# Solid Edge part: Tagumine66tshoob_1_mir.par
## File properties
Author: KULL
Template: Iso Metric Part.par
Last saved by: KULL
Revision: 2
Application: Solid Edge
Density: 2712,000 kg/m^3
Accuracy: 0,990
Username: KULL
Material: Aluminum, 1060
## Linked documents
Tagumine66tshoob_1.par
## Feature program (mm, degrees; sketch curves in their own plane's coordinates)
part copy "CopiedPart_1"
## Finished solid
Body 1: solid body, 578 faces, 1234 edges, 670 vertices.
  Faces by surface: blend 365, spline 59, sphere 55, plane 30, cylinder 28, torus 27, offset 13, cone 1
  Edges by curve: intersection 729, circle 467, line 37, curve on surface 1
Bounding box of the edges (mm; curved faces can reach further): 84.000 x 73.183 x 18.177, from (-384.46, -113.1829, -2.3663) to (-300.46, -40, 15.811).
Cylindrical faces by radius (mm): R0.4 x6, R1.5 x1, R2.5 x2, R2.9732 x1, R5 x4, R7 x2, R7.9504 x1, R8.5905 x1, R9.9504 x1, R10.5905 x1, R10.611 x1, R12.611 x1, R20 x2, R21.7545 x1, R22 x2, R23.7545 x1
Conical faces (half-angle, radius in mm at the cone's reference point): 40.1033 deg R3.865 x1
Toroidal faces (ring radius, tube radius in mm): R2.5732 r0.4 x2, R3.9041 r0.4 x1, R4.4 r0.6 x8, R4.5371 r1.485 x1, R4.996 r0.6 x1, R5.3 r0.3 x8, R5.7982 r0.6 x1, R6 r1 x4, R6.9857 r1 x1
Spherical faces by radius (mm): R0.1 x53, R4 x1, R6 x1
Planar faces by outward normal: +x 9, -x 9, oblique 12
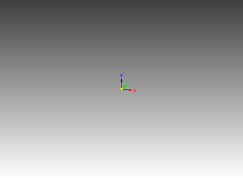
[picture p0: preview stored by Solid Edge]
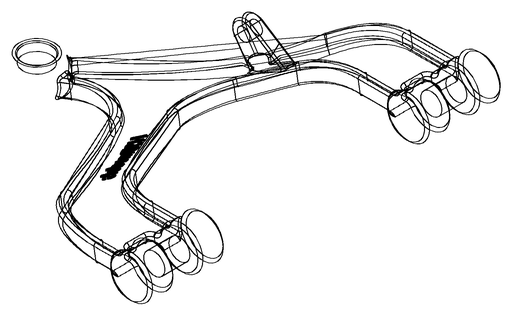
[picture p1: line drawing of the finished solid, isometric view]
